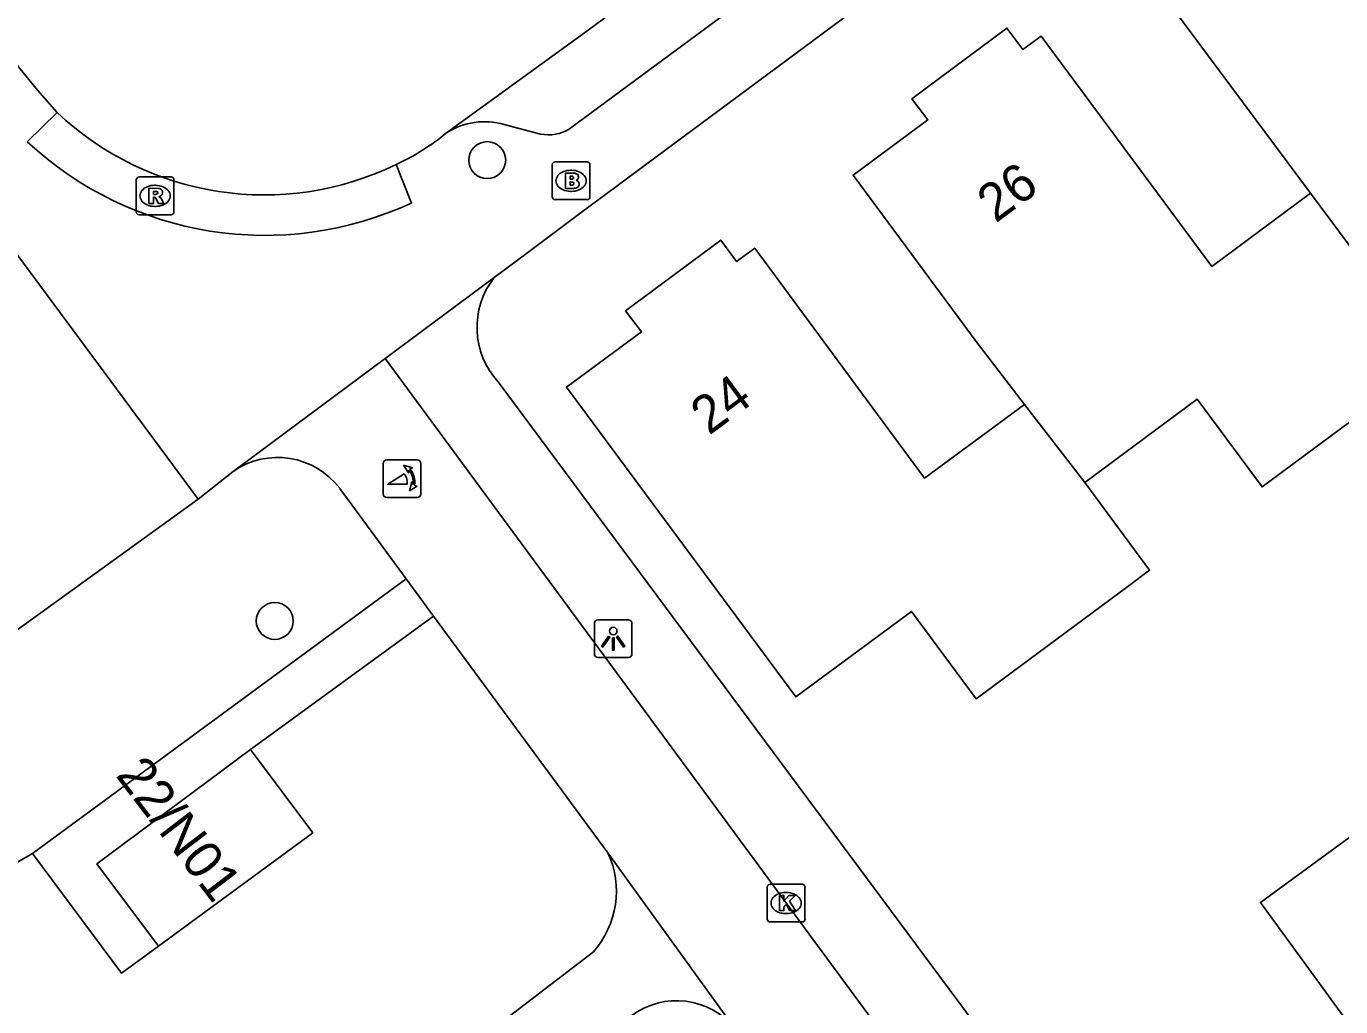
# Model space of a CAD drawing. Extents: x 163427 to 164190, y 380331 to 381641.
# Drawn here: x 163869.78 to 163904.63, y 381101.66 to 381127.66 of the extents above; entities that cross this region are included whole.
import ezdxf

# ---------------------------------------------------------------- set-up
doc = ezdxf.new("R2010")
doc.units = 0
for name, color, linetype in [('IMGEO_Boom', 7, 'Continuous'), ('IMGEO_Brandkraan', 7, 'Continuous'), ('IMGEO_Fietspad_open', 7, 'Continuous'), ('IMGEO_Groenvoorziening', 7, 'Continuous'), ('IMGEO_Kolk', 7, 'Continuous'), ('IMGEO_Lichtpunt', 7, 'Continuous'), ('IMGEO_Pand', 7, 'Continuous'), ('IMGEO_Pand_nummerreeks', 7, 'Continuous'), ('IMGEO_Poller', 7, 'Continuous'), ('IMGEO_Rijbaan_lokaal_open', 7, 'Continuous'), ('IMGEO_Rioolput', 7, 'Continuous'), ('IMGEO_Voetpad_halfverhard', 7, 'Continuous'), ('IMGEO_Voetpad_open', 7, 'Continuous')]:
    doc.layers.add(name, color=color, linetype=linetype)

msp = doc.modelspace()

# ---------------------------------------------------------------- linework, layer by layer
at = {"layer": 'IMGEO_Boom'}
for centre in [(163882.003, 381124.108), (163876.369, 381111.89)]:
    msp.add_circle(centre, 0.489, dxfattribs=at)
at = {"layer": 'IMGEO_Brandkraan'}
for p, q in [((163883.725, 381123.133), (163883.725, 381123.985)), ((163883.8, 381124.059), (163884.652, 381124.059)), ((163884.726, 381123.985), (163884.726, 381123.133)), ((163884.213, 381123.839), (163884.238, 381123.839)), ((163884.236, 381123.279), (163884.211, 381123.279)), ((163884.652, 381123.059), (163883.8, 381123.059))]:
    msp.add_line(p, q, dxfattribs=at)
for points in [[(163883.725, 381123.133), (163883.725, 381123.985)], [(163883.8, 381124.059), (163884.652, 381124.059)], [(163884.726, 381123.985), (163884.726, 381123.133)], [(163884.073, 381123.759), (163884.073, 381123.359), (163884.286, 381123.359)], [(163884.304, 381123.759), (163884.073, 381123.759)], [(163884.252, 381123.678), (163884.198, 381123.678), (163884.198, 381123.602)], [(163884.198, 381123.602), (163884.251, 381123.602)], [(163884.26, 381123.526), (163884.198, 381123.526), (163884.198, 381123.445)], [(163884.198, 381123.445), (163884.26, 381123.445)], [(163884.652, 381123.059), (163883.8, 381123.059)]]:
    msp.add_lwpolyline(points, dxfattribs=at)
for centre, radius, start, end in [((163883.802, 381123.983), 0.0765, 91.552, 178.448), ((163883.802, 381123.983), 0.0765, 91.552, 178.448), ((163884.65, 381123.983), 0.0765, 1.552, 88.448), ((163884.65, 381123.983), 0.0765, 1.552, 88.448), ((163884.253, 381123.64), 0.0379, 267.8285, 90.9355), ((163884.308, 381123.614), 0.145, 59.4692, 91.5367), ((163884.333, 381123.661), 0.0922, 285.5137, 58.1501), ((163884.338, 381123.469), 0.105, 301.3115, 78.989), ((163884.261, 381123.485), 0.0404, 269.8759, 90.5077), ((163884.292, 381123.61), 0.251, 268.6676, 293.5347), ((163883.802, 381123.135), 0.0765, 181.552, 268.448), ((163883.802, 381123.135), 0.0765, 181.552, 268.448), ((163884.65, 381123.135), 0.0765, 271.552, 358.448), ((163884.65, 381123.135), 0.0765, 271.552, 358.448)]:
    msp.add_arc(centre, radius, start, end, dxfattribs=at)
for centre, major_axis, ratio, start_param, end_param in [((163884.212, 381123.559), (-0.387, 0.002), 0.722429, 4.712389, 7.853982), ((163884.237, 381123.559), (-0.39, 0.002), 0.717154, 1.570796, 4.712389)]:
    msp.add_ellipse(centre, major_axis=major_axis, ratio=ratio, start_param=start_param, end_param=end_param, dxfattribs=at)
at = {"layer": 'IMGEO_Fietspad_open'}
for points in [[(163875.27, 381115.855), (163879.294, 381118.846)], [(163879.294, 381118.846), (163916.003, 381069.011), (163920.063, 381063.521)], [(163878.091, 381115.406), (163879.855, 381113.008)], [(163879.855, 381113.008), (163880.581, 381112.021)], [(163880.581, 381112.021), (163885.203, 381105.739)], [(163885.203, 381105.739), (163888.584, 381101.063)]]:
    msp.add_lwpolyline(points, dxfattribs=at)
msp.add_arc((163876.447, 381114.165), 2.06, 37.0526, 124.8603, dxfattribs=at)
at = {"layer": 'IMGEO_Groenvoorziening'}
for points in [[(163874.338, 381115.123), (163867.872, 381110.455), (163866.166, 381109.192)], [(163848.379, 381095.943), (163850.493, 381094.839), (163851.753, 381095.363), (163853.983, 381093.322), (163867.256, 381104.176), (163869.951, 381105.722)]]:
    msp.add_lwpolyline(points, dxfattribs=at)
at = {"layer": 'IMGEO_Kolk'}
for p, q in [((163889.425, 381103.985), (163889.425, 381104.837)), ((163889.5, 381104.911), (163890.352, 381104.911)), ((163890.426, 381104.837), (163890.426, 381103.985)), ((163889.913, 381104.691), (163889.938, 381104.691)), ((163889.936, 381104.131), (163889.911, 381104.131)), ((163890.352, 381103.911), (163889.5, 381103.911))]:
    msp.add_line(p, q, dxfattribs=at)
for points in [[(163889.425, 381103.985), (163889.425, 381104.837)], [(163889.5, 381104.911), (163890.352, 381104.911)], [(163890.426, 381104.837), (163890.426, 381103.985)], [(163889.746, 381104.611), (163889.869, 381104.611), (163889.869, 381104.46), (163889.999, 381104.611), (163890.163, 381104.611), (163890.017, 381104.46), (163890.17, 381104.211), (163890.018, 381104.211), (163889.933, 381104.375), (163889.869, 381104.308), (163889.869, 381104.211), (163889.746, 381104.211), (163889.746, 381104.611)], [(163890.352, 381103.911), (163889.5, 381103.911)]]:
    msp.add_lwpolyline(points, dxfattribs=at)
for centre, start, end in [((163889.502, 381104.835), 91.552, 178.448), ((163889.502, 381104.835), 91.552, 178.448), ((163890.35, 381104.835), 1.552, 88.448), ((163890.35, 381104.835), 1.552, 88.448), ((163889.502, 381103.987), 181.552, 268.448), ((163889.502, 381103.987), 181.552, 268.448), ((163890.35, 381103.987), 271.552, 358.448), ((163890.35, 381103.987), 271.552, 358.448)]:
    msp.add_arc(centre, 0.0765, start, end, dxfattribs=at)
for centre, major_axis, ratio, start_param, end_param in [((163889.912, 381104.411), (-0.387, 0.002), 0.722429, 4.712389, 7.853982), ((163889.937, 381104.411), (-0.39, 0.002), 0.717154, 1.570796, 4.712389)]:
    msp.add_ellipse(centre, major_axis=major_axis, ratio=ratio, start_param=start_param, end_param=end_param, dxfattribs=at)
at = {"layer": 'IMGEO_Lichtpunt'}
for p, q in [((163884.843, 381111.825), (163884.843, 381111.018)), ((163884.843, 381111.825), (163884.843, 381111.018)), ((163885.745, 381111.92), (163884.937, 381111.92)), ((163885.745, 381111.92), (163884.937, 381111.92)), ((163885.839, 381111.018), (163885.839, 381111.825)), ((163885.839, 381111.018), (163885.839, 381111.825)), ((163884.937, 381110.924), (163885.745, 381110.924)), ((163884.937, 381110.924), (163885.745, 381110.924))]:
    msp.add_line(p, q, dxfattribs=at)
for points in [[(163885.217, 381111.489), (163885.256, 381111.461), (163885.068, 381111.199), (163885.03, 381111.226), (163885.217, 381111.489)], [(163885.319, 381111.441), (163885.366, 381111.441), (163885.366, 381111.119), (163885.319, 381111.119), (163885.319, 381111.441)], [(163885.429, 381111.461), (163885.467, 381111.488), (163885.654, 381111.226), (163885.615, 381111.198), (163885.429, 381111.461)]]:
    msp.add_lwpolyline(points, dxfattribs=at)
msp.add_circle((163885.342, 381111.623), 0.0994, dxfattribs=at)
for centre, start, end in [((163884.937, 381111.825), 90, 180), ((163884.937, 381111.825), 90, 180), ((163885.745, 381111.825), 0, 90), ((163885.745, 381111.825), 0, 90), ((163884.937, 381111.018), 180, 270), ((163884.937, 381111.018), 180, 270), ((163885.745, 381111.018), 270, 0), ((163885.745, 381111.018), 270, 360)]:
    msp.add_arc(centre, 0.0946, start, end, dxfattribs=at)
at = {"layer": 'IMGEO_Pand'}
for points in [[(163911.457, 381128.826), (163908.835, 381126.878), (163907.537, 381128.624), (163904.279, 381133.006), (163903.797, 381132.65), (163903.374, 381133.22), (163900.854, 381131.347), (163901.27, 381130.787), (163899.295, 381129.331), (163903.828, 381123.229)], [(163903.828, 381123.229), (163901.215, 381121.29), (163899.951, 381122.993), (163896.685, 381127.394), (163896.203, 381127.038), (163895.78, 381127.608), (163893.26, 381125.735), (163893.678, 381125.171), (163891.703, 381123.71), (163894.963, 381119.295), (163896.246, 381117.63)], [(163903.828, 381123.229), (163907.102, 381118.82)], [(163896.246, 381117.63), (163893.598, 381115.675), (163892.35, 381117.365), (163889.096, 381121.772), (163888.614, 381121.416), (163888.191, 381121.986), (163885.671, 381120.113), (163886.088, 381119.551), (163884.102, 381118.084), (163890.183, 381109.877), (163893.245, 381112.145), (163894.961, 381109.828), (163898.98, 381112.804), (163899.563, 381113.236), (163897.841, 381115.561)], [(163897.841, 381115.561), (163900.823, 381117.77), (163902.545, 381115.445), (163907.102, 381118.82)], [(163896.246, 381117.63), (163897.841, 381115.561)], [(163875.725, 381108.486), (163871.655, 381105.448), (163873.284, 381103.268)], [(163875.725, 381108.486), (163877.378, 381106.277), (163873.284, 381103.268)], [(163907.553, 381102.419), (163905.209, 381100.711), (163902.5, 381104.428), (163904.843, 381106.137), (163907.553, 381102.419)]]:
    msp.add_lwpolyline(points, dxfattribs=at)
at = {"layer": 'IMGEO_Poller'}
for p, q in [((163879.245, 381116.064), (163879.245, 381115.257)), ((163879.245, 381116.064), (163879.245, 381115.257)), ((163880.147, 381116.159), (163879.339, 381116.159)), ((163880.147, 381116.159), (163879.339, 381116.159)), ((163880.241, 381115.257), (163880.241, 381116.064)), ((163880.241, 381115.257), (163880.241, 381116.064)), ((163879.339, 381115.162), (163880.147, 381115.162)), ((163879.339, 381115.162), (163880.147, 381115.162))]:
    msp.add_line(p, q, dxfattribs=at)
for points in [[(163879.924, 381115.888), (163879.912, 381115.815), (163879.787, 381116.02)], [(163879.787, 381116.02), (163880.018, 381115.954), (163879.947, 381115.922)], [(163879.88, 381115.515), (163879.367, 381115.515), (163879.797, 381115.79)], [(163879.94, 381115.343), (163880.006, 381115.574), (163880.036, 381115.506)], [(163880.072, 381115.479), (163880.144, 381115.468), (163879.94, 381115.343)]]:
    msp.add_lwpolyline(points, dxfattribs=at)
for centre, radius, start, end in [((163879.339, 381116.064), 0.0946, 90, 180), ((163879.339, 381116.064), 0.0946, 90, 180), ((163879.566, 381115.575), 0.516, 349.3569, 42.2912), ((163880.147, 381116.064), 0.0946, 0, 90), ((163880.147, 381116.064), 0.0946, 0, 90), ((163879.552, 381115.565), 0.332, 351.3247, 42.4854), ((163879.566, 381115.575), 0.476, 351.7527, 41.1691), ((163879.339, 381115.257), 0.0946, 180, 270), ((163879.339, 381115.257), 0.0946, 180, 270), ((163880.147, 381115.257), 0.0946, 270, 0), ((163880.147, 381115.257), 0.0946, 270, 0)]:
    msp.add_arc(centre, radius, start, end, dxfattribs=at)
at = {"layer": 'IMGEO_Rijbaan_lokaal_open'}
for points in [[(163880.923, 381124.832), (163884.68, 381127.548), (163916.554, 381151.141)], [(163870.604, 381125.37), (163870.078, 381125.96), (163869.579, 381126.581), (163869.504, 381126.682)]]:
    msp.add_lwpolyline(points, dxfattribs=at)
for centre, radius, start, end in [((163876.089, 381131.157), 7.973, 226.5387, 296.0332), ((163877.19, 381129.291), 5.815, 294.3562, 309.9396)]:
    msp.add_arc(centre, radius, start, end, dxfattribs=at)
at = {"layer": 'IMGEO_Rioolput'}
for p, q in [((163872.697, 381122.734), (163872.697, 381123.586)), ((163872.772, 381123.66), (163873.624, 381123.66)), ((163873.698, 381123.586), (163873.698, 381122.734)), ((163873.185, 381123.44), (163873.21, 381123.44)), ((163873.208, 381122.88), (163873.183, 381122.88)), ((163873.624, 381122.66), (163872.772, 381122.66))]:
    msp.add_line(p, q, dxfattribs=at)
for points in [[(163872.697, 381122.734), (163872.697, 381123.586)], [(163872.772, 381123.66), (163873.624, 381123.66)], [(163873.698, 381123.586), (163873.698, 381122.734)], [(163873.286, 381123.358), (163873.034, 381123.36), (163873.034, 381122.96)], [(163873.212, 381123.279), (163873.158, 381123.279), (163873.158, 381123.198)], [(163873.034, 381122.96), (163873.158, 381122.96), (163873.158, 381123.122), (163873.169, 381123.122)], [(163873.158, 381123.198), (163873.21, 381123.198)], [(163873.216, 381123.093), (163873.287, 381122.96), (163873.427, 381122.96), (163873.362, 381123.086)], [(163873.624, 381122.66), (163872.772, 381122.66)]]:
    msp.add_lwpolyline(points, dxfattribs=at)
for centre, radius, start, end in [((163872.774, 381123.584), 0.0765, 91.552, 178.448), ((163872.774, 381123.584), 0.0765, 91.552, 178.448), ((163873.622, 381123.584), 0.0765, 1.552, 88.448), ((163873.622, 381123.584), 0.0765, 1.552, 88.448), ((163873.218, 381123.183), 0.0964, 77.0061, 93.1865), ((163873.232, 381123.24), 0.0378, 276.6634, 79.6772), ((163873.285, 381123.248), 0.109, 350.3612, 89.416), ((163873.283, 381123.248), 0.112, 277.5842, 350.9817), ((163873.168, 381123.069), 0.0533, 26.0293, 88.6989), ((163873.194, 381123.387), 0.19, 274.7715, 282.9687), ((163873.267, 381123.033), 0.108, 29.5134, 73.7905), ((163872.774, 381122.736), 0.0765, 181.552, 268.448), ((163872.774, 381122.736), 0.0765, 181.552, 268.448), ((163873.622, 381122.736), 0.0765, 271.552, 358.448), ((163873.622, 381122.736), 0.0765, 271.552, 358.448)]:
    msp.add_arc(centre, radius, start, end, dxfattribs=at)
for centre, major_axis, ratio, start_param, end_param in [((163873.184, 381123.16), (-0.387, 0.002), 0.722429, 4.712389, 7.853982), ((163873.209, 381123.16), (-0.39, 0.002), 0.717154, 1.570796, 4.712389)]:
    msp.add_ellipse(centre, major_axis=major_axis, ratio=ratio, start_param=start_param, end_param=end_param, dxfattribs=at)
at = {"layer": 'IMGEO_Voetpad_halfverhard'}
msp.add_lwpolyline([(163860.665, 381084.431), (163863.932, 381087.182), (163869.42, 381091.331), (163875.557, 381096.043), (163881.424, 381100.523), (163884.816, 381103.12)], dxfattribs=at)
for centre, radius, start, end in [((163883.009, 381104.725), 2.417, 318.3836, 24.8053), ((163887.024, 381099.846), 1.978, 37.9623, 127.7622)]:
    msp.add_arc(centre, radius, start, end, dxfattribs=at)
at = {"layer": 'IMGEO_Voetpad_open'}
for points in [[(163915.45, 381148.075), (163911.422, 381145.095), (163908.391, 381142.852), (163903.871, 381139.507), (163900.842, 381137.267), (163896.214, 381133.842), (163893.166, 381131.587), (163888.806, 381128.36), (163885.739, 381126.089), (163884.183, 381124.937)], [(163882.189, 381120.998), (163883.08, 381121.66), (163884.455, 381122.693), (163917.22, 381146.987)], [(163854.6, 381141.786), (163874.338, 381115.123)], [(163869.81, 381124.596), (163870.604, 381125.37)], [(163883.418, 381124.799), (163882.448, 381125.048)], [(163879.588, 381123.993), (163879.991, 381122.97)], [(163882.189, 381120.998), (163879.294, 381118.846)], [(163899.274, 381095.308), (163898.019, 381097.05), (163882.295, 381118.226)], [(163874.338, 381115.123), (163875.27, 381115.855)], [(163869.951, 381105.722), (163879.855, 381113.008)], [(163880.581, 381112.021), (163875.725, 381108.486)], [(163873.284, 381103.268), (163872.309, 381102.549), (163869.951, 381105.722)]]:
    msp.add_lwpolyline(points, dxfattribs=at)
for centre, radius, start, end in [((163881.92, 381123.283), 1.843, 73.3575, 122.766), ((163883.629, 381125.819), 1.042, 258.3193, 302.1322), ((163876.106, 381131.332), 9.22, 226.9326, 294.9193), ((163883.866, 381119.674), 2.136, 141.7043, 222.6755)]:
    msp.add_arc(centre, radius, start, end, dxfattribs=at)

# ---------------------------------------------------------------- texts
at = {"layer": 'IMGEO_Pand_nummerreeks'}
for s, rotation, p in [('26', 36.4802, (163895.479, 381122.423)), ('24', 36.4458, (163887.883, 381116.798)), ('22/N01', 307.4506, (163872.131, 381107.795))]:
    msp.add_text(s, height=1, rotation=rotation, dxfattribs=at).set_placement(p)

doc.saveas('drawing.dxf')
